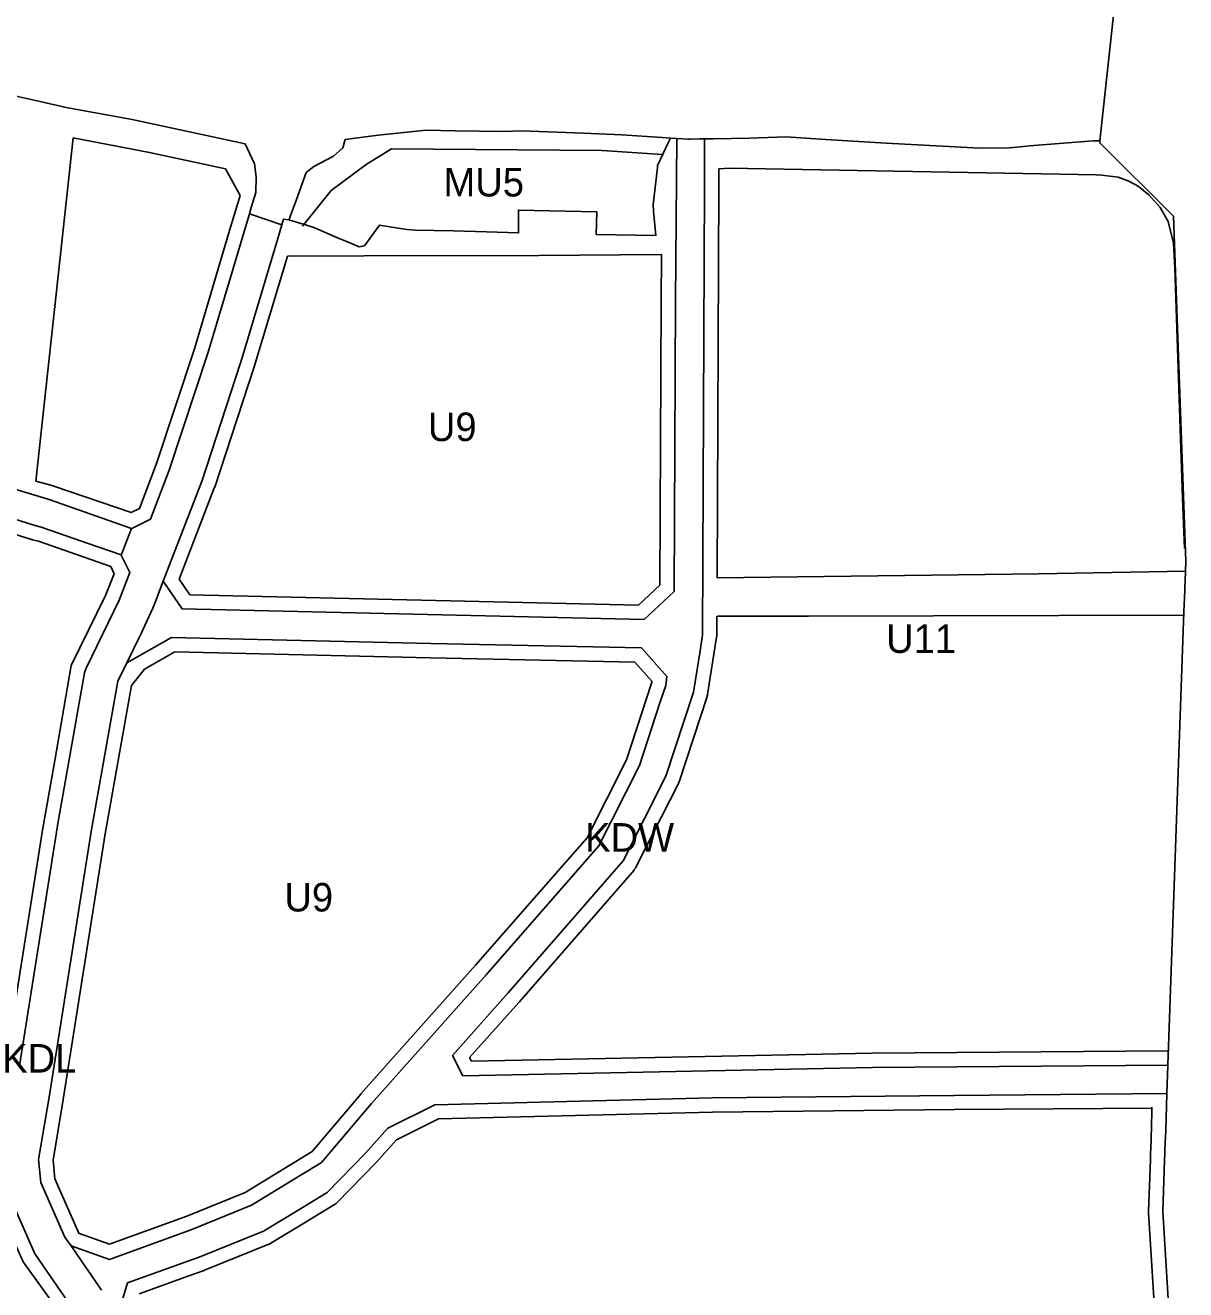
# Model space of a CAD drawing. Extents: x 7425930 to 7427318, y 5544765 to 5546387.
# Drawn here: x 7426698.5 to 7427105.6, y 5545008.8 to 5545452.3 of the extents above; entities that cross this region are included whole.
import ezdxf

# ---------------------------------------------------------------- set-up
doc = ezdxf.new("R2010")
doc.units = 0
for name, color, linetype in [('linie_rozgraniczajace', 7, 'Continuous'), ('linie_zabudowy_nieprzekraczalne', 7, 'Continuous'), ('linie_zabudowy_obowiazujace', 7, 'Continuous'), ('oznaczenia_przeznaczen', 7, 'Continuous')]:
    doc.layers.add(name, color=color, linetype=linetype)

msp = doc.modelspace()

# ---------------------------------------------------------------- linework, layer by layer
at = {"layer": 'linie_rozgraniczajace'}
for points in [[(7427080.8, 5545461.42), (7427075.49, 5545411.78), (7427073.13, 5545411.82), (7427050.81, 5545410.03), (7427046.45, 5545409.64), (7427043.77, 5545409.4), (7427033.28, 5545409.2), (7427028.96, 5545409.44), (7427000.43, 5545411), (7426979.31, 5545412.29), (7426965.27, 5545413.15), (7426952.55, 5545412.78), (7426939.8, 5545412.56), (7426936.79, 5545412.51), (7426935.01, 5545412.48), (7426931.79, 5545412.42), (7426931.13, 5545412.41), (7426926.99, 5545412.66), (7426924.83, 5545412.79), (7426921.9, 5545412.97), (7426907.72, 5545413.86), (7426894.25, 5545414.55), (7426872.45, 5545415.31), (7426866.35, 5545415.03), (7426849.3, 5545415.26), (7426839.13, 5545415.52), (7426822.27, 5545413.79), (7426810.72, 5545412.28), (7426809.83, 5545409.36), (7426806.61, 5545406.47), (7426799.69, 5545402.8), (7426796.99, 5545400.66), (7426793.58, 5545391.18), (7426791.43, 5545385.23), (7426791.02, 5545384.08), (7426790.96, 5545384.05), (7426790.93, 5545384.06), (7426789.02, 5545384.29), (7426788.46, 5545382.39), (7426777.1, 5545386.2), (7426777.75, 5545388.39), (7426779.34, 5545393.68), (7426779.42, 5545399.15), (7426778.92, 5545403.71), (7426775.64, 5545410.7), (7426735.92, 5545419.34), (7426712.78, 5545423.5), (7426704.2, 5545425.45), (7426691.68, 5545428.29)], [(7426691.68, 5545428.29), (7426704.2, 5545425.45), (7426712.78, 5545423.5), (7426735.92, 5545419.34), (7426775.64, 5545410.7), (7426778.92, 5545403.71), (7426779.42, 5545399.15), (7426779.34, 5545393.68), (7426777.75, 5545388.39), (7426777.1, 5545386.2), (7426762.58, 5545337.62), (7426748.98, 5545296.24), (7426742.36, 5545279.05), (7426735.8, 5545275.85), (7426735.75, 5545275.8), (7426735.72, 5545275.81), (7426706.86, 5545286), (7426673.73, 5545295.93)], [(7426725.19, 5545008.68), (7426721.67, 5545013.77), (7426720.12, 5545016.02), (7426720.12, 5545016.04), (7426720.12, 5545016.05), (7426719.8, 5545016.51), (7426714.51, 5545024.25), (7426727.96, 5545019.45), (7426756.92, 5545029.89), (7426777.84, 5545038.47), (7426802.43, 5545053.46), (7426819.95, 5545074.15), (7426860.18, 5545119.28), (7426891.66, 5545155.3), (7426899.71, 5545164.51), (7426913.96, 5545192.73), (7426921.24, 5545214.97), (7426923.14, 5545220.76), (7426923.54, 5545223.89), (7426914.59, 5545233.91), (7426840.69, 5545235.43), (7426749.73, 5545237.55), (7426734.07, 5545228.74), (7426738.37, 5545237.55), (7426739.3, 5545239.45), (7426740.44, 5545241.78), (7426740.45, 5545241.78), (7426743.2, 5545247.84), (7426743.19, 5545247.84), (7426744.1, 5545250.2), (7426746.87, 5545257.38), (7426753.46, 5545247.6), (7426915.54, 5545243.91), (7426926.09, 5545253.76), (7426926.56, 5545355.45), (7426926.99, 5545412.66), (7426931.13, 5545412.41), (7426931.79, 5545412.42), (7426935.01, 5545412.48), (7426936.79, 5545412.51), (7426936.72, 5545395.95), (7426936.07, 5545238.53), (7426935.19, 5545232.96), (7426932.89, 5545218.41), (7426923.23, 5545188.89), (7426908.24, 5545159.29), (7426867.91, 5545112.92), (7426848.36, 5545090.99), (7426851.95, 5545083.88), (7426995.65, 5545086.72), (7427099.35, 5545087.61), (7427098.99, 5545077.6), (7427024.37, 5545076.96), (7426939.43, 5545076.06), (7426842.19, 5545073.68), (7426825.6, 5545065.47), (7426817.82, 5545056.74), (7426804.35, 5545042.92), (7426793.84, 5545036.51), (7426782.04, 5545029.39), (7426759.51, 5545020.23), (7426754.18, 5545018.33), (7426734.33, 5545011.24), (7426731.07, 5545000.18)], [(7426696.47, 5545087.37), (7426709.77, 5545171.52), (7426709.79, 5545171.57), (7426709.79, 5545171.62), (7426719.27, 5545225.23), (7426719.54, 5545226.26), (7426719.78, 5545226.82), (7426731.4, 5545250.63), (7426735.15, 5545260.34), (7426732.13, 5545266.47), (7426735.72, 5545275.81), (7426735.75, 5545275.8), (7426735.8, 5545275.85), (7426742.36, 5545279.05), (7426748.98, 5545296.24), (7426762.58, 5545337.62), (7426777.1, 5545386.2), (7426788.46, 5545382.39), (7426787.03, 5545377.51), (7426774.05, 5545334.11), (7426774.02, 5545334.04), (7426774, 5545333.95), (7426760.34, 5545292.35), (7426760.26, 5545292.22), (7426760.23, 5545292.07), (7426746.87, 5545257.38), (7426744.1, 5545250.2), (7426743.19, 5545247.84), (7426743.2, 5545247.84), (7426740.45, 5545241.78), (7426740.44, 5545241.78), (7426739.3, 5545239.45), (7426738.37, 5545237.55), (7426734.07, 5545228.74), (7426730.94, 5545222.31), (7426721.62, 5545169.59), (7426706.88, 5545076.37), (7426706.87, 5545076.33), (7426706.87, 5545076.3), (7426703.15, 5545054.42), (7426703.91, 5545046.41), (7426712.33, 5545027.27), (7426714.07, 5545024.76), (7426714.16, 5545024.77), (7426714.51, 5545024.25), (7426719.8, 5545016.51), (7426720.12, 5545016.05), (7426720.12, 5545016.04), (7426720.12, 5545016.02), (7426721.67, 5545013.77), (7426725.19, 5545008.68)], [(7426673.73, 5545295.93), (7426706.86, 5545286), (7426735.72, 5545275.81), (7426732.13, 5545266.47), (7426732.08, 5545266.55), (7426720.47, 5545270.6), (7426704.78, 5545276.09), (7426704.53, 5545276.17), (7426702.26, 5545276.73), (7426665.69, 5545288.13)], [(7426665.69, 5545288.13), (7426702.26, 5545276.73), (7426704.53, 5545276.17), (7426704.78, 5545276.09), (7426720.47, 5545270.6), (7426732.08, 5545266.55), (7426732.13, 5545266.47), (7426735.15, 5545260.34), (7426731.4, 5545250.63), (7426719.78, 5545226.82), (7426719.54, 5545226.26), (7426719.27, 5545225.23), (7426709.79, 5545171.62), (7426709.79, 5545171.57), (7426709.77, 5545171.52), (7426696.47, 5545087.37)], [(7426731.07, 5545000.18), (7426734.33, 5545011.24), (7426754.18, 5545018.33), (7426759.51, 5545020.23), (7426782.04, 5545029.39), (7426793.84, 5545036.51), (7426804.35, 5545042.92), (7426817.82, 5545056.74), (7426825.6, 5545065.47), (7426842.19, 5545073.68), (7426939.43, 5545076.06), (7427024.37, 5545076.96), (7427098.99, 5545077.6), (7427098.54, 5545064.65), (7427098.46, 5545062.47), (7427098.3, 5545057.89), (7427098.25, 5545056.48), (7427098.25, 5545056.47), (7427098.17, 5545054.22), (7427097.53, 5545036.19), (7427099.73, 5544999.86)], [(7426715.65, 5545001.38), (7426702.14, 5545020.92), (7426701.63, 5545021.81), (7426701.61, 5545021.87), (7426701.58, 5545021.92), (7426692.54, 5545042.47), (7426692.43, 5545042.95), (7426692.06, 5545044.32)], [(7426692.54, 5545042.47), (7426701.58, 5545021.92), (7426701.61, 5545021.87), (7426701.63, 5545021.81), (7426702.14, 5545020.92), (7426715.65, 5545001.38)]]:
    msp.add_lwpolyline(points, dxfattribs=at)
for points in [[(7426746.87, 5545257.38), (7426760.23, 5545292.07), (7426760.26, 5545292.22), (7426760.34, 5545292.35), (7426774, 5545333.95), (7426774.02, 5545334.04), (7426774.05, 5545334.11), (7426787.03, 5545377.51), (7426788.46, 5545382.39), (7426789.02, 5545384.29), (7426790.93, 5545384.06), (7426790.96, 5545384.05), (7426791, 5545384.04), (7426791, 5545384.03), (7426792.14, 5545383.7), (7426798.58, 5545381.76), (7426800.03, 5545381.32), (7426803.41, 5545379.8), (7426808.56, 5545377.55), (7426811.47, 5545376.34), (7426815.6, 5545374.63), (7426817.45, 5545375), (7426822.72, 5545382.21), (7426829.22, 5545381.15), (7426832.38, 5545380.7), (7426835.32, 5545380.49), (7426841.9, 5545380.34), (7426848.66, 5545380.28), (7426860.29, 5545379.87), (7426871.55, 5545379.48), (7426871.49, 5545387.5), (7426898.93, 5545386.92), (7426898.75, 5545378.9), (7426919.7, 5545378.61), (7426918.91, 5545387.11), (7426918.69, 5545389.4), (7426920.21, 5545402.47), (7426920.29, 5545403.15), (7426922.26, 5545407.34), (7426923.92, 5545410.88), (7426924.82, 5545412.78), (7426924.83, 5545412.79), (7426926.99, 5545412.66), (7426926.56, 5545355.45), (7426926.09, 5545253.76), (7426915.54, 5545243.91), (7426753.46, 5545247.6)], [(7426790.96, 5545384.05), (7426791.02, 5545384.08), (7426791.43, 5545385.23), (7426793.58, 5545391.18), (7426796.99, 5545400.66), (7426799.69, 5545402.8), (7426806.61, 5545406.47), (7426809.83, 5545409.36), (7426810.72, 5545412.28), (7426822.27, 5545413.79), (7426839.13, 5545415.52), (7426849.3, 5545415.26), (7426866.35, 5545415.03), (7426872.45, 5545415.31), (7426894.25, 5545414.55), (7426907.72, 5545413.86), (7426921.9, 5545412.97), (7426924.83, 5545412.79), (7426924.82, 5545412.78), (7426923.92, 5545410.88), (7426922.26, 5545407.34), (7426920.29, 5545403.15), (7426920.21, 5545402.47), (7426918.69, 5545389.4), (7426918.91, 5545387.11), (7426919.7, 5545378.61), (7426898.75, 5545378.9), (7426898.93, 5545386.92), (7426871.49, 5545387.5), (7426871.55, 5545379.48), (7426860.29, 5545379.87), (7426848.66, 5545380.28), (7426841.9, 5545380.34), (7426835.32, 5545380.49), (7426832.38, 5545380.7), (7426829.22, 5545381.15), (7426822.72, 5545382.21), (7426817.45, 5545375), (7426815.6, 5545374.63), (7426811.47, 5545376.34), (7426808.56, 5545377.55), (7426803.41, 5545379.8), (7426800.03, 5545381.32), (7426798.58, 5545381.76), (7426792.14, 5545383.7), (7426791, 5545384.03), (7426791, 5545384.04)], [(7426848.36, 5545090.99), (7426867.91, 5545112.92), (7426908.24, 5545159.29), (7426923.23, 5545188.89), (7426932.89, 5545218.41), (7426935.19, 5545232.96), (7426936.07, 5545238.53), (7426936.72, 5545395.95), (7426936.79, 5545412.51), (7426939.8, 5545412.56), (7426952.55, 5545412.78), (7426965.27, 5545413.15), (7426979.31, 5545412.29), (7427000.43, 5545411), (7427028.96, 5545409.44), (7427033.28, 5545409.2), (7427043.77, 5545409.4), (7427046.45, 5545409.64), (7427050.81, 5545410.03), (7427073.13, 5545411.82), (7427075.49, 5545411.78), (7427075.46, 5545411.53), (7427075.42, 5545411.1), (7427101.3, 5545385.36), (7427105.57, 5545264.4), (7427105.33, 5545257.39), (7427105.24, 5545255.1), (7427105.21, 5545254.12), (7427105.03, 5545249.09), (7427104.95, 5545246.63), (7427099.35, 5545087.61), (7426995.65, 5545086.72), (7426851.95, 5545083.88)], [(7426703.15, 5545054.42), (7426706.87, 5545076.3), (7426706.87, 5545076.33), (7426706.88, 5545076.37), (7426721.62, 5545169.59), (7426730.94, 5545222.31), (7426734.07, 5545228.74), (7426749.73, 5545237.55), (7426840.69, 5545235.43), (7426914.59, 5545233.91), (7426923.54, 5545223.89), (7426923.14, 5545220.76), (7426921.24, 5545214.97), (7426913.96, 5545192.73), (7426899.71, 5545164.51), (7426891.66, 5545155.3), (7426860.18, 5545119.28), (7426819.95, 5545074.15), (7426802.43, 5545053.46), (7426777.84, 5545038.47), (7426756.92, 5545029.89), (7426727.96, 5545019.45), (7426714.51, 5545024.25), (7426714.16, 5545024.77), (7426714.07, 5545024.76), (7426712.33, 5545027.27), (7426703.91, 5545046.41)]]:
    msp.add_lwpolyline(points, close=True, dxfattribs=at)
at = {"layer": 'linie_zabudowy_nieprzekraczalne'}
for points in [[(7426715.29, 5545412.83), (7426702.16, 5545292.46), (7426708.3, 5545290.78), (7426708.52, 5545290.71), (7426735.58, 5545281.4), (7426738.56, 5545282.85), (7426744.5, 5545298.57), (7426757.82, 5545338.83), (7426770.11, 5545380.3), (7426773.84, 5545392.63)], [(7426921.88, 5545407.02), (7426900.83, 5545408.39), (7426826.82, 5545409.03), (7426826.81, 5545409.02), (7426826.95, 5545408.94), (7426818.02, 5545403.5), (7426805.72, 5545394.37), (7426795.77, 5545381.87)], [(7426941.75, 5545401.93), (7426941.72, 5545395.93)], [(7426941.72, 5545395.93), (7426941.15, 5545258.46)], [(7426941.72, 5545395.93), (7426941.72, 5545395.93)], [(7426941.72, 5545395.93), (7426941.72, 5545395.93)], [(7426921.67, 5545371.9), (7426878.65, 5545371.56), (7426817.39, 5545371.41), (7426790.4, 5545371.35)], [(7426921.56, 5545355.49), (7426921.67, 5545371.9), (7426921.56, 5545355.49)], [(7426790.4, 5545371.35), (7426778.8, 5545332.52), (7426764.91, 5545290.27), (7426764.64, 5545289.8)], [(7426921.1, 5545255.94), (7426921.56, 5545355.47)], [(7426921.56, 5545355.47), (7426921.56, 5545355.49)], [(7426764.89, 5545290.26), (7426752.47, 5545258.02)], [(7426729.69, 5545259.96), (7426728.47, 5545262.5), (7426718.73, 5545265.91), (7426703.04, 5545271.39), (7426703.02, 5545271.4), (7426700.98, 5545271.89), (7426700.75, 5545271.95), (7426700.67, 5545271.98), (7426664.11, 5545283.38)], [(7426941.16, 5545258.54), (7427053.92, 5545259.94), (7427105.45, 5545260.9)], [(7426693.47, 5545100.38), (7426704.48, 5545170.01), (7426708.85, 5545194.48), (7426714.51, 5545227.81), (7426726.62, 5545252.26), (7426729.69, 5545259.96)], [(7426752.46, 5545258.03), (7426756.16, 5545252.54)], [(7426756.16, 5545252.54), (7426913.61, 5545248.96)], [(7426913.61, 5545248.96), (7426921.1, 5545255.94)], [(7426941.1, 5545245.05), (7426941.07, 5545238.51)], [(7427104.9, 5545245.43), (7426973.23, 5545245.09), (7426941.3, 5545245.01)], [(7426941.01, 5545237.75), (7426937.83, 5545217.63)], [(7426941.05, 5545238.08), (7426941.01, 5545237.76)], [(7426941.01, 5545237.76), (7426941.01, 5545237.75)], [(7426941.07, 5545238.41), (7426941.05, 5545238.08)], [(7426941.07, 5545238.51), (7426941.07, 5545238.41)], [(7426750.98, 5545232.52), (7426740.24, 5545226.48)], [(7426840.57, 5545230.43), (7426750.98, 5545232.52)], [(7426840.58, 5545230.43), (7426840.57, 5545230.43)], [(7426912.31, 5545228.96), (7426840.58, 5545230.43)], [(7426740.24, 5545226.48), (7426735.73, 5545220.74), (7426726.54, 5545168.76), (7426711.8, 5545075.52), (7426708.19, 5545054.23), (7426708.81, 5545047.68), (7426717.21, 5545028.59)], [(7426918.29, 5545222.26), (7426912.31, 5545228.96)], [(7426909.33, 5545194.64), (7426918.24, 5545221.87)], [(7426918.24, 5545221.87), (7426918.29, 5545222.26)], [(7426937.64, 5545216.86), (7426927.98, 5545187.34)], [(7426937.68, 5545217), (7426937.64, 5545216.86)], [(7426937.77, 5545217.32), (7426937.68, 5545217)], [(7426937.83, 5545217.63), (7426937.77, 5545217.32)], [(7426895.53, 5545167.32), (7426909.33, 5545194.64)], [(7426927.69, 5545186.64), (7426912.7, 5545157.03)], [(7426927.8, 5545186.87), (7426927.69, 5545186.64)], [(7426927.92, 5545187.17), (7426927.8, 5545186.87)], [(7426927.98, 5545187.34), (7426927.92, 5545187.17)], [(7426887.9, 5545158.59), (7426895.53, 5545167.32)], [(7426856.44, 5545122.59), (7426887.9, 5545158.59)], [(7426912.02, 5545156.01), (7426871.69, 5545109.64)], [(7426887.9, 5545158.59), (7426887.9, 5545158.59)], [(7426912.13, 5545156.15), (7426912.02, 5545156.01)], [(7426912.33, 5545156.41), (7426912.13, 5545156.15)], [(7426912.51, 5545156.69), (7426912.33, 5545156.41)], [(7426912.67, 5545156.97), (7426912.51, 5545156.69)], [(7426912.7, 5545157.03), (7426912.67, 5545156.97)], [(7426816.22, 5545077.48), (7426856.44, 5545122.59)], [(7426871.64, 5545109.59), (7426854.36, 5545090.21)], [(7426871.69, 5545109.64), (7426871.64, 5545109.59)], [(7426995.6, 5545091.72), (7427099.47, 5545092.6)], [(7426854.36, 5545090.21), (7426855, 5545088.94)], [(7426855, 5545088.94), (7426995.55, 5545091.72)], [(7426995.55, 5545091.72), (7426995.6, 5545091.72)], [(7426799.14, 5545057.3), (7426816.13, 5545077.38)], [(7426816.13, 5545077.38), (7426816.22, 5545077.48)], [(7426939.52, 5545071.06), (7426843.42, 5545068.71)], [(7427024.42, 5545071.96), (7426939.52, 5545071.06)], [(7427093.97, 5545072.51), (7427024.42, 5545071.96)], [(7427094.58, 5545002.06), (7427092.54, 5545035.88), (7427092.53, 5545036.12), (7427092.53, 5545036.36), (7427093.17, 5545054.39), (7427093.17, 5545054.39), (7427093.22, 5545055.79), (7427093.24, 5545056.49), (7427093.25, 5545056.58), (7427093.25, 5545056.62), (7427093.25, 5545056.64), (7427093.25, 5545056.64), (7427093.25, 5545056.64), (7427093.25, 5545056.64), (7427093.25, 5545056.64), (7427093.25, 5545056.64), (7427093.25, 5545056.64), (7427093.25, 5545056.64), (7427093.25, 5545056.65), (7427093.25, 5545056.68), (7427093.26, 5545056.9), (7427093.27, 5545057.34), (7427093.29, 5545057.78), (7427093.3, 5545058), (7427093.3, 5545058.05), (7427093.3, 5545058.07), (7427093.3, 5545058.1), (7427093.3, 5545058.14), (7427093.3, 5545058.23), (7427093.32, 5545058.59), (7427093.42, 5545061.44), (7427093.44, 5545062.16), (7427093.45, 5545062.51), (7427093.46, 5545062.6), (7427093.46, 5545062.64), (7427093.46, 5545062.66), (7427093.46, 5545062.75), (7427093.49, 5545063.43), (7427093.53, 5545064.79), (7427093.72, 5545072.83)], [(7426843.42, 5545068.71), (7426828.69, 5545061.42)], [(7426828.69, 5545061.42), (7426821.55, 5545053.41)], [(7426858.11, 5544805.51), (7426838.33, 5544831.26), (7426800.21, 5544878.94), (7426791.21, 5544889.94), (7426760.21, 5544929.31), (7426764.88, 5544933.06), (7426730.1, 5544977.78), (7426723.05, 5544985.09), (7426715.52, 5544993.89), (7426697.67, 5545018.58), (7426687.92, 5545040.29), (7426687.14, 5545043.3), (7426686.1, 5545055.84), (7426685.97, 5545059.25)], [(7426775.58, 5545042.94), (7426799.14, 5545057.3)], [(7426821.4, 5545053.25), (7426807.93, 5545039.43)], [(7426821.49, 5545053.35), (7426821.4, 5545053.25)], [(7426821.55, 5545053.41), (7426821.49, 5545053.35)], [(7426755.12, 5545034.56), (7426775.58, 5545042.94)], [(7426807.8, 5545039.3), (7426807.56, 5545039.08)], [(7426807.93, 5545039.43), (7426807.8, 5545039.3)], [(7426806.96, 5545038.65), (7426796.44, 5545032.24)], [(7426807.03, 5545038.69), (7426806.96, 5545038.65)], [(7426807.3, 5545038.88), (7426807.03, 5545038.69)], [(7426807.56, 5545039.08), (7426807.3, 5545038.88)], [(7426727.95, 5545024.76), (7426755.12, 5545034.56)], [(7426796.42, 5545032.23), (7426784.62, 5545025.11)], [(7426796.44, 5545032.24), (7426796.42, 5545032.23)], [(7426717.09, 5545028.63), (7426727.95, 5545024.76)], [(7426783.92, 5545024.76), (7426761.39, 5545015.6)], [(7426784.14, 5545024.85), (7426783.92, 5545024.76)], [(7426784.43, 5545025), (7426784.14, 5545024.85)], [(7426784.62, 5545025.11), (7426784.43, 5545025)], [(7426755.86, 5545013.62), (7426738.41, 5545007.38)], [(7426761.19, 5545015.53), (7426755.86, 5545013.62)], [(7426761.3, 5545015.57), (7426761.19, 5545015.53)], [(7426761.39, 5545015.6), (7426761.3, 5545015.57)]]:
    msp.add_lwpolyline(points, dxfattribs=at)
at = {"layer": 'linie_zabudowy_obowiazujace'}
for points in [[(7426773.84, 5545392.63), (7426768.67, 5545401.93), (7426742.09, 5545407.74), (7426715.29, 5545412.83)], [(7426945.4, 5545402.19), (7426941.75, 5545401.93)], [(7427105.17, 5545268.77), (7427104.45, 5545286.49), (7427101.7, 5545367.04), (7427101.34, 5545375.92), (7427099.38, 5545383.46), (7427096.57, 5545388.39), (7427092.78, 5545392.7), (7427088.85, 5545395.91), (7427085.57, 5545397.6), (7427081.92, 5545399.06), (7427076.15, 5545399.71), (7427074.1, 5545399.84), (7426945.4, 5545402.19)]]:
    msp.add_lwpolyline(points, dxfattribs=at)

# ---------------------------------------------------------------- texts
at = {"layer": 'oznaczenia_przeznaczen'}
for s, p in [('MU5', (7426845.19, 5545392.29)), ('U9', (7426839.71, 5545306.49)), ('U11', (7427000.46, 5545232.17)), ('KDW', (7426894.87, 5545162.47)), ('U9', (7426789.36, 5545141.48)), ('KDL', (7426690.35, 5545084.97))]:
    msp.add_text(s, height=10, dxfattribs=at).set_placement(p)

doc.saveas('drawing.dxf')
